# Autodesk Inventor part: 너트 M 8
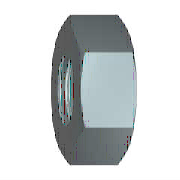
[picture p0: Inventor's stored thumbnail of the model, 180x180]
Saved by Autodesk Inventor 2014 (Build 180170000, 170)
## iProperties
IsCustomPart: 1
Created: 2012-02
Part Number: 너트 M 8
Material: 강철, 연강
Description: 6각 너트 및 6각 가는 너트
Document SubType Name: Modeling
Standard: KS B 1012
Designer: mduedu
Standards Organization: KS
Language: ko-KR
Size Designation: M 8
Categories: <MemberInstance><Categories><Category DisplayName="조임쇠" InternalName="e4da775c-781d-43d5-af7c-5136215cf5a6" Mnemonic="FSTN"><Category DisplayName="너트" InternalN
Density: 1 g/cm^3
Appearance: Steel
Author: mduedu
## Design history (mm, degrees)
sketch "스케치1"
  geometry: L1 (-7.506, 0)-(-3.753, 6.5); L2 (-3.753, 6.5)-(3.753, 6.5); L3 (3.753, 6.5)-(7.506, 0); L4 (7.506, 0)-(3.753, -6.5); L5 (3.753, -6.5)-(-3.753, -6.5); L6 (-3.753, -6.5)-(-7.506, 0); 2 further points
  constraints: 12 end point, 1 coincident, 1 horizontal, 11 other
  dimensions: "d0" = 15.01111 distance of L3.end L1.start (= 1.1547 x SW)
extrude "본체" new body sketch "스케치1" distance "d1" = 5 (= KOH); taper "d2" = 0 deg
sketch "스케치2"
  geometry: L1 (0, 3.753)-(0, 7.506) reference; L2 (0, 7.506)-(5, 7.506) reference; L3 (5, 3.753)-(5, 7.506) reference; L4 (-1, 0)-(6, 0) reference; L5 (0.581, 7.506)-(0, 6.5); L6 (4.419, 7.506)-(5, 6.5)
  constraints: 4 end point, 4 point on line
  dimensions: "d3" = 30 deg angle of L1 L5 (= ANG1); "d4" = 30 deg angle of L3 L6 (= ANG2); "d5" = 13 diameter of L5.end L4 (= SW0); "d6" = 13 diameter of L6.end L4 (= SW01)
revolve "모따기1" sketch "스케치2" stored, may be unused: angle "d7" = 90 deg
sketch "스케치3"
  geometry: A1 r 6.5 centre (0, 0) between (-3.25, -5.629) and (3.25, -5.629) reference; 1 further point
  constraints: 1 coincident
hole "스레드" sketch "스케치3" at (0, 0) diameter "d25" = 6.647; stored, may be unused: countersink angle "d29" = 82 deg, drill point angle "d31" = 118 deg; dims "d26" = 6, "d27" = 4, "d28" = 2, "d30" = 8
workaxis "Work Axis1"
workplane "Work Plane1"
body "Solid1"
chamfer "모따기2" distance "d8" = 0.67658 (= -0.5 x GD1 + 0.5 x NND); stored, may be unused: angle "d9" = 30 deg, second distance "d40" = 0.67658 (= -0.5 x GD1 + 0.5 x NND)
chamfer "모따기3" distance "d10" = 0.67658 (= -0.5 x GD1 + 0.5 x NND); stored, may be unused: angle "d11" = 30 deg, second distance "d41" = 0.67658 (= -0.5 x GD1 + 0.5 x NND)
other parameters: "ANG1" = 30 deg [user parameter; used in 1 equation term], "ANG2" = 30 deg [user parameter; used in 1 equation term], "NND" = 8 [user parameter; used in 4 equation terms], "KOH" = 5 [user parameter; used in 1 equation term], "SW" = 13 [user parameter; used in 4 equation terms], "SW0" = 13 (= SW) [user parameter; used in 1 equation term], "SW01" = 13 (= SW) [user parameter; used in 1 equation term], "GD1" = 6.64684 (computed from THREADDIA, PTC, TOA) [user parameter; used in 4 equation terms], "d13" = 0, "d14" = 0, "d39" = 0, "d42" = 0, "GUL" = 0.67658 (= 0.541266 x PTC) [user parameter], "TPU" = 8 (computed from PTC) [user parameter], "THREADDIA" = 8 [user parameter; used in 1 equation term], "TOA" = 30 deg [user parameter; used in 1 equation term], "PTC" = 1.25 [user parameter; used in 4 equation terms], "E0" = 15.015 (= 1.155 x SW) [user parameter], "GAL" = 0.67658 (= 0.541266 x PTC) [user parameter]
